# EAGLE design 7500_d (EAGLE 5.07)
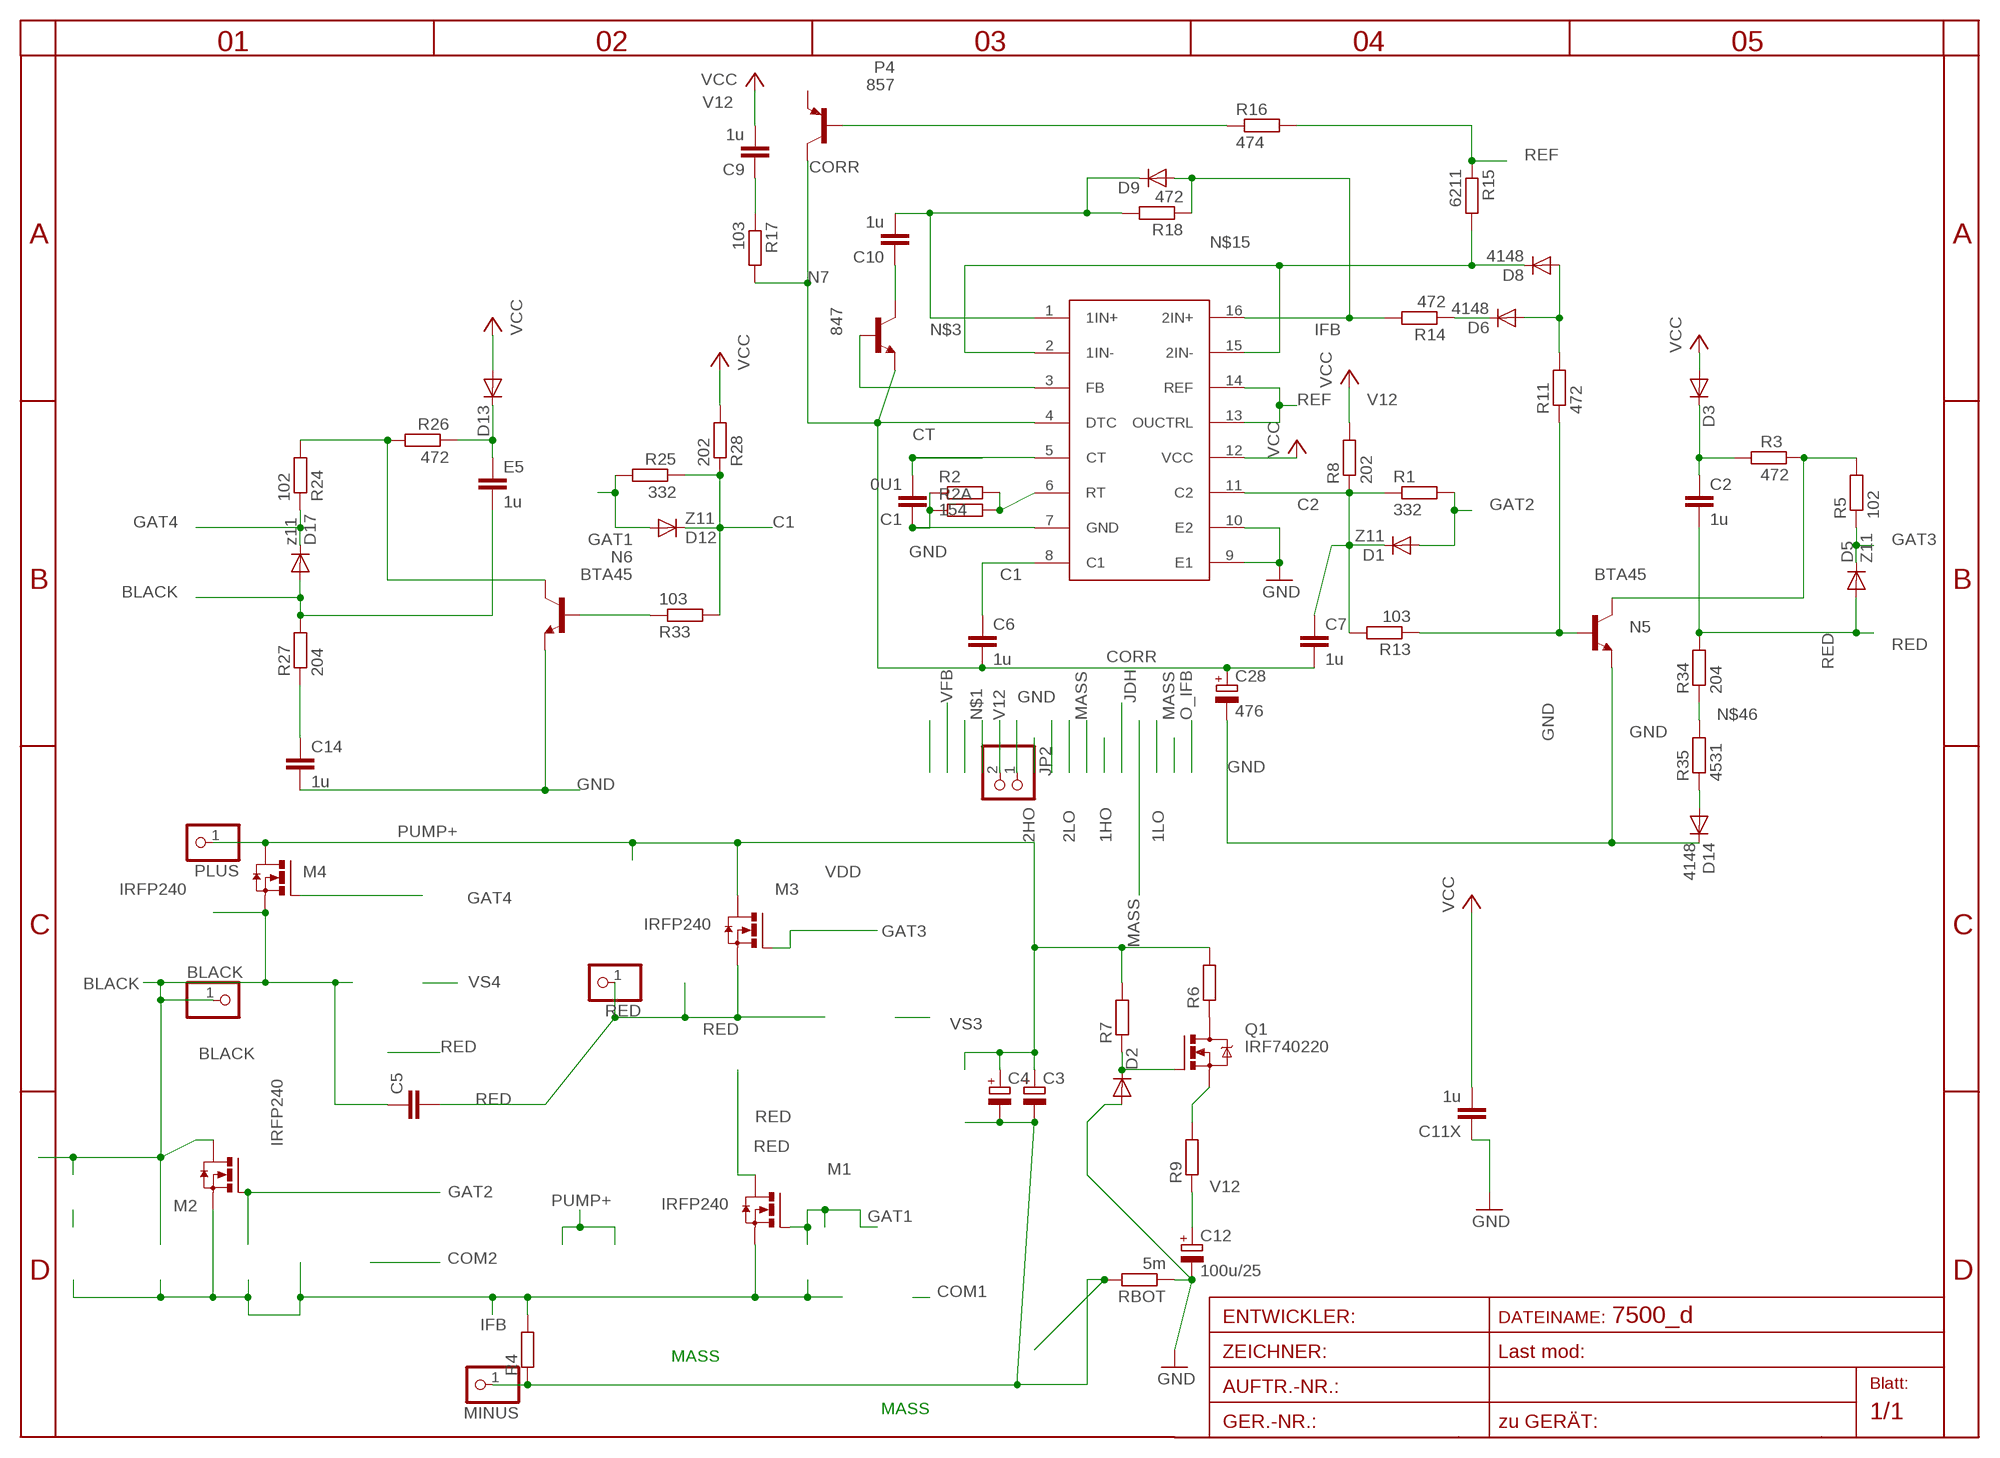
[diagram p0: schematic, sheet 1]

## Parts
7500  AZ7500SO16  [SO16]
BLACK  PINHD-1X12MM2  [1X2MM2]
C1  0U1  C-EUC0805  [C0805]
C2  1u  C-EUC1206  [C1206]
C3  CPOL-EUE5-13  [E5-13]
C4  CPOL-EUE5-13  [E5-13]
C5  C-EU050-024X044  [C050-024X044]
C6  1u  C-EUC0805  [C0805]
C7  1u  C-EUC0805  [C0805]
C9  1u  C-EUC0805  [C0805]
C10  1u  C-EUC1206  [C1206]
C11X  1u  C-EUC1206  [C1206]
C12  100u/25  CPOL-EUD  [PANASONIC_D]
C14  1u  C-EUC1206  [C1206]
C28  476  CPOL-EUA  [PANASONIC_A]
D1  Z11  DIODE-MINIMELF  [MINIMELF]
D2  DIODE-MINIMELF  [MINIMELF]
D3  DIODE-SMA-DO214  [SMA-DO214AC]
D5  Z11  DIODE-MINIMELF  [MINIMELF]
D6  4148  DIODE-MINIMELF  [MINIMELF]
D8  4148  DIODE-MINIMELF  [MINIMELF]
D9  DIODE-MINIMELF  [MINIMELF]
D12  Z11  DIODE-MINIMELF  [MINIMELF]
D13  DIODE-SMA-DO214  [SMA-DO214AC]
D14  4148  DIODE-MINIMELF  [MINIMELF]
D17  z11  DIODE-MINIMELF  [MINIMELF]
E5  1u  C-EUC1206  [C1206]
JP2  PINHD-1X2STR  [1X02]
M1  IRFP240  [TO247BV]
M2  IRFP240  [TO247BV]
M3  IRFP240  [TO247BV]
M4  IRFP240  [TO247BV]
MINUS  PINHD-1X12MM2  [1X2MM2]
N5  BTA45  SMBTA45HV  [SOT23HV]
N6  BTA45  SMBTA45HV  [SOT23HV]
N7  847  BC847ALT1SMD  [SOT23]
P4  857  BC857ALT1SMD  [SOT23-BEC]
PLUS  PINHD-1X12MM2  [1X2MM2]
Q1  IRF740220  [TO220BV]
R1  332  R-EU_R0805  [R0805]
R2  154  R-EU_R0805  [R0805]
R2A  R-EU_R0805  [R0805]
R3  472  R-EU_R0805  [R0805]
R4  R-EU_0309/10  [0309/10]
R5  102  R-EU_R1206  [R1206]
R6  R-EU_0207/10  [0207/10]
R7  R-EU_0207/10  [0207/10]
R8  202  R-EU_R0805  [R0805]
R9  R-EU_0207/12  [0207/12]
R11  472  R-EU_R0805  [R0805]
R13  103  R-EU_R0805  [R0805]
R14  472  R-EU_R0805  [R0805]
R15  6211  R-EU_R1206  [R1206]
R16  474  R-EU_R1206  [R1206]
R17  103  R-EU_R1206  [R1206]
R18  472  R-EU_R0805  [R0805]
R24  102  R-EU_R1206  [R1206]
R25  332  R-EU_R0805  [R0805]
R26  472  R-EU_R0805  [R0805]
R27  204  R-EU_R1206  [R1206]
R28  202  R-EU_R0805  [R0805]
R33  103  R-EU_R0805  [R0805]
R34  204  R-EU_R0805  [R0805]
R35  4531  R-EU_R0805  [R0805]
RBOT  5m  R-EU_0204/5  [0204/5]
RED  PINHD-1X12MM2  [1X2MM2]

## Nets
BLACK: BLACK.1 C5.1 D17.A E5.2 M2.D M4.S R27.2
C1: 7500.8(C1) C6.1 D12.C R25.1 R28.1 R33.2
C2: 7500.11(C2) C7.1 D1.C R1.1 R8.1 R13.2
CORR: 7500.4(DTC) C6.2 C7.2 C28.+ N7.2(E) P4.C R17.2
CT: 7500.5(CT) C1.2
GAT1: D12.A M1.G R25.2
GAT2: D1.A M2.G R1.2
GAT3: D5.C M3.G R5.1
GAT4: D17.C M4.G R24.1
GND: 7500.7(GND) 7500.9(E1) 7500.10(E2) C1.1 C11X.1 C12.- C14.2 C28.- D2.A D14.C JP2.1 N5.2(E) N6.2(E) R2.1 R2A.1 RBOT.1
IFB: 7500.16(2IN+) D9.A M1.S M2.S R4.2 R14.2 R18.1
MASS: C3.- C4.- MINUS.1 R4.1 RBOT.2
N$3: 7500.1(1IN+) C10.2 D9.C R18.2
N$4: C2.1 D3.K(C) R3.1
N$5: N5.3(C) R3.2 R5.2
N$7: Q1.D R6.1
N$8: D2.C Q1.G R7.1
N$11: N5.1(B) R11.1 R13.1
N$13: D6.A D8.A R11.2
N$15: 7500.2(1IN-) 7500.15(2IN-) D8.C R15.2
N$36: D6.C R14.1
N$37: P4.B R16.1
N$38: 7500.6(RT) R2.2 R2A.2
N$39: C9.1 R17.1
N$40: 7500.3(FB) N7.1(B)
N$41: C10.1 N7.3(C)
N$42: D13.K(C) E5.1 R26.1
N$43: N6.3(C) R24.2 R26.2
N$44: N6.1(B) R33.1
N$45: C14.1 R27.1
N$46: R34.1 R35.2
N$47: D14.A R35.1
PUMP+: C3.+ C4.+ M3.D M4.D PLUS.1 R6.2 R7.2
RED: C2.2 C5.2 D5.A M1.D M3.S R34.2 RED.1
REF: 7500.13(OUCTRL) 7500.14(REF) R15.1 R16.2
V12: 7500.12(VCC) C9.2 C11X.2 C12.+ D3.A D13.A JP2.2 R8.2 R9.1 R28.2 ; supply symbol labelled VCC
WAE: Q1.S R9.2
Unconnected: P4.E

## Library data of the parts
7500 = az7500:AZ7500
BLACK MINUS PLUS RED = pinhead:PINHD-1X1: PIN HEADER
C1 C2 C5-C7 C9 C10 C11X C14 E5 = rcl:C-EU: CAPACITOR, European symbol
C3 C4 C12 C28 = rcl:CPOL-EU: POLARIZED CAPACITOR, European symbol
D1-D3 D5 D6 D8 D9 D12-D14 D17 = diode:DIODE-: DIODE
JP2 = pinhead:PINHD-1X2: PIN HEADER
M1-M4 = transistor-power:IRFP240: HEXFET Power MosFet Source: http://www.irf.com/
N5 N6 = transistor-npn:SMBTA45
N7 = transistor-npn:BC847*: NPN Transistor
P4 = transistor-pnp:BC857*: PNP Transistror
Q1 = transistor-power:IRF740: N-CHANNEL MOS FET
R1 R2 R2A R3-R9 R11 R13-R18 R24-R28 R33-R35 RBOT = rcl:R-EU_: RESISTOR, European symbol

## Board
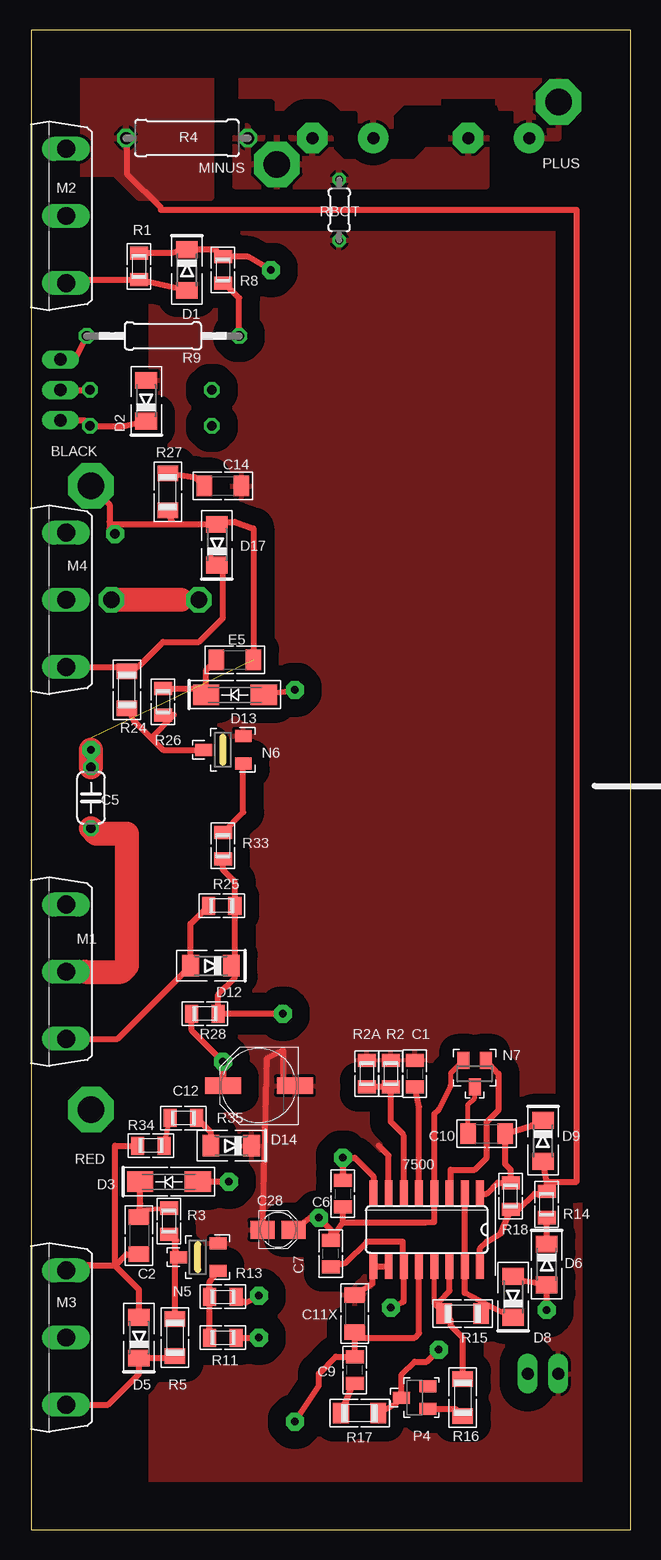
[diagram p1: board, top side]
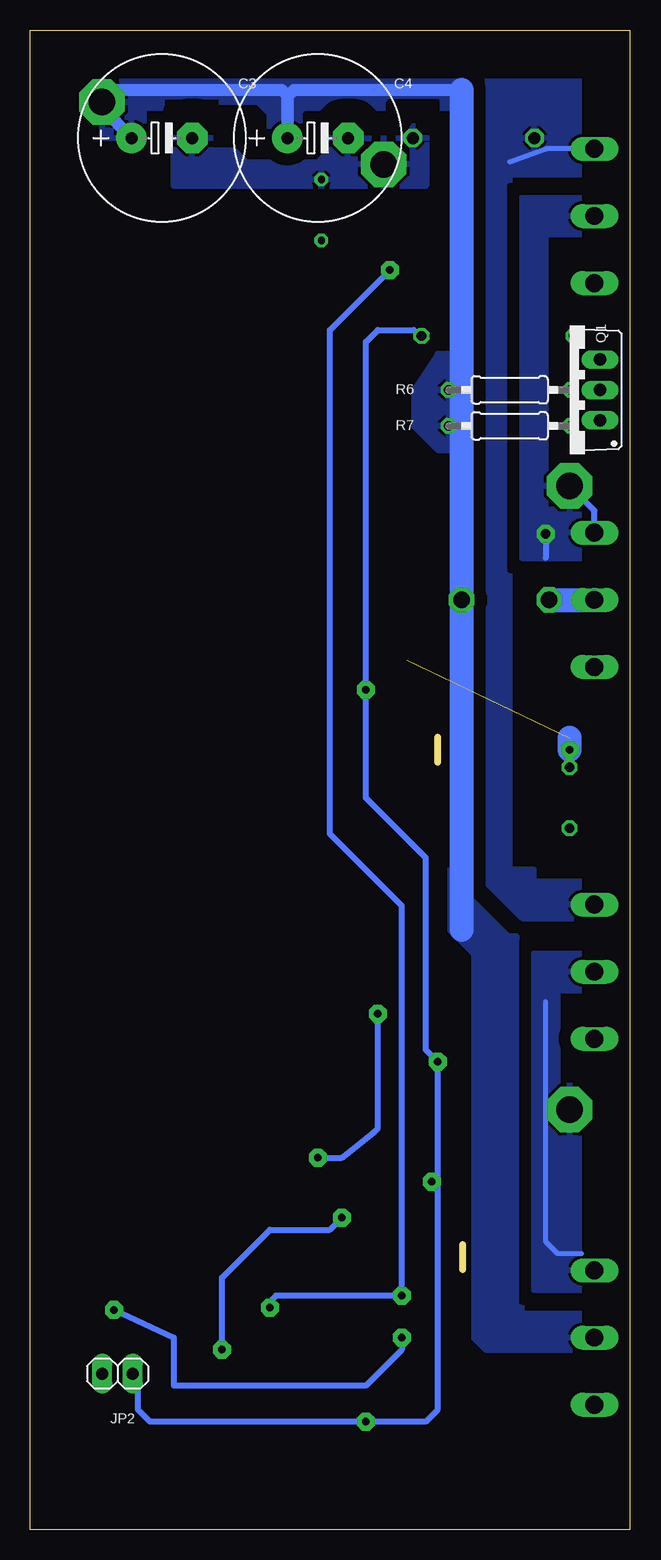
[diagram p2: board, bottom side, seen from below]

Size 50 x 125 mm. Coordinates in mm from the lower left corner, seen from the top.
Outline: 0,0 50,0 50,125 0,125 0,0
Copper layers (1*16): Top 0.035mm / dielectric 1.5mm / Bottom 0.035mm
Design rules "default *": minimum track width 10mil, minimum drill 20mil, track to track 8mil, track to pad 8mil, pad to pad 8mil, via to via 8mil, smd to smd 8mil, copper to edge 4mm, drill to drill 8mil, minimum pad ring 10mil, minimum via ring 8mil, stop-mask expansion 4mil, vias tented up to drill 0mil, thermal gap 10mil

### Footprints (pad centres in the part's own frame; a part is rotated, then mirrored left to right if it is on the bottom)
SO16 = smd 2.032 x 0.66: 1 -3.073,4.445; 2 -3.073,3.175; 3 -3.073,1.905; 4 -3.073,0.635; 5 -3.073,-0.635; 6 -3.073,-1.905; 7 -3.073,-3.175; 8 -3.073,-4.445; 9 3.073,-4.445; 10 3.073,-3.175; 11 3.073,-1.905; 12 3.073,-0.635; 13 3.073,0.635; 14 3.073,1.905; 15 3.073,3.175; 16 3.073,4.445
1X2MM2 = drill 2.2 pad 3.81 octagon: 1 0,0
C0805 = smd 1.1 x 1.5: 1 -1.1,0; 2 1.1,0
C1206 = smd 1.3 x 1.7: 1 -1.55,0; 2 1.55,0
E5-13 = drill 1 pad 2.54 round: + -2.54,0 | drill 1 pad 2.54 octagon: - 2.54,0
C050-024X044 = drill 0.8 octagon: 1 -2.54,0; 2 2.54,0
PANASONIC_D = smd 3 x 1.4: + 3,0; - -3,0
PANASONIC_A = smd 2 x 1.5: + 1.3,0; - -1.3,0
MINIMELF = smd 1.4 x 1.8: A 1.7,0; C -1.7,0
SMA-DO214AC = smd 2.2 x 1.7: A 2.4,0; K -2.4,0
1X02 = drill 1 pad 1.676 long: 1 -1.27,0; 2 1.27,0
TO247BV = drill 1.499 long: D 0,-2.921; G -5.588,-2.921; S 5.588,-2.921
SOT23HV = smd 1 x 1.4: 1 -1.15,-1.7; 2 1.15,-1.7; 3 0,1.6
SOT23 = smd 1 x 1.4: 1 -0.95,-1.1; 2 0.95,-1.1; 3 0,1.1
SOT23-BEC = smd 1 x 1.4: B -0.95,-1.1; C 0,1.1; E 0.95,-1.1
TO220BV = drill 1.016 long: D 0,-2.54; G -2.54,-2.54; S 2.54,-2.54
R0805 = smd 1.1 x 1.5: 1 -1.1,0; 2 1.1,0
0309/10 = drill 1 octagon: 1 -5.08,0; 2 5.08,0
R1206 = smd 1.3 x 1.7: 1 -1.55,0; 2 1.55,0
0207/10 = drill 0.8 octagon: 1 -5.08,0; 2 5.08,0
0207/12 = drill 0.813 octagon: 1 -6.35,0; 2 6.35,0
0204/5 = drill 0.6 octagon: 1 -2.54,0; 2 2.54,0

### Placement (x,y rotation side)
7500  33,25 270 top
BLACK  5,87 0 top
C1  32,38 270 top
C2  9,24.5 270 top
C3  39,116 0 bottom
C4  26,116 0 bottom
C5  5,61 270 top
C6  26,28 270 top
C7  25,23 90 top
C9  27,13.3 90 top
C10  38,33 0 top
C11X  27,18 270 top
C12  19,37 180 top
C14  16,87 0 top
C28  20.6,25 0 top
D1  13,105 270 top
D2  9.6,94.1 90 top
D3  11.5,29 0 top
D5  9,16 90 top
D6  43,22.1 270 top
D8  40.2,19.4 90 top
D9  42.7,32.4 270 top
D12  15,47 180 top
D13  17,69.6 0 top
D14  16.7,32 180 top
D17  15.5,82.1 90 top
E5  17,72.5 0 top
JP2  42.7,13 0 bottom
M1  0,46.5 90 top
M2  0,109.5 90 top
M3  0,16 90 top
M4  0,77.5 90 top
MINUS  20.5,113.8 0 top
N5  13.9,22.7 90 top
N6  16,65 90 top
N7  37,38 180 top
P4  32,11 90 top
PLUS  44,119 0 top
Q1  5,95 90 bottom
R1  9,105.3 270 top
R2  30,38 270 top
R2A  28,38 270 top
R3  11.5,25.7 270 top
R4  13,116 180 top
R5  12,16 90 top
R6  10,95 180 bottom
R7  10,92 180 bottom
R8  16,105 270 top
R9  11,99.5 180 top
R11  16,16 0 top
R13  16,19.4 0 top
R14  43,27.1 90 top
R15  36,18 0 top
R16  36,11 90 top
R17  27.4,9.7 0 top
R18  40,27.8 90 top
R24  8,70 270 top
R25  15.9,52 180 top
R26  11,69 270 top
R27  11.4,86.5 270 top
R28  14.5,43 180 top
R33  16,57 270 top
R34  10,32 180 top
R35  12.7,34.3 180 top
RBOT  25.7,110 90 top
RED  5,35 0 top

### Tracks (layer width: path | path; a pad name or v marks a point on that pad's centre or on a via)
BLACK  (via drill 0.6 pad 1.5, 0.8 pad 1.5)  (1 unrouted)
  Top 0.5: E5.2 18.55,83.45 17,84 16.1,84 D17.A 11.85,83.8 | 11.85,83.8 R27.2 | BLACK.1 6.55,85.45 6.55,84 | 6.55,84 6.55,83.45 v7,83 | 11.85,83.8 6.75,83.8 6.55,84
  Top 2: C5.1 v5,65
  Bottom 0.5: M4.S 2.92,84.92 BLACK.1 | v7,83 7,81
  Bottom 2: v5,65 5,66
  pour Bottom (isolate 1): 2,111 9,111 9,81 1,81 1,85 7,85 7,108 1,108 1,109
C1  (via drill 0.6 pad 1.5)
  Top 0.5: 7500.8 28.55,29.45 27,31 26.1,31 C6.1 v26,31 | v21,43 R28.1 15.6,44.6 17,46 17,46.7 D12.C 17,47.3 R25.1 17,54 16,55 R33.2
  Bottom 0.5: v26,31 24,31 21.33,33.12 21,33.45 v21,43
C2  (via drill 0.6 pad 1.5)
  Top 0.5: R13.2 17.9,18.9 v19,19.5 | v30,18.5 31,19 31.09,19 7500.11 31,22.02 31,24 28,24 26.2,22.2 C7.1 | v20,105 18.1,106.1 R8.1 15.4,106.7 D1.C 11.7,106.4 R1.1
  Bottom 0.5: v20,105 25,100 25,58 19,52 v19,19.5 29.5,19.5 30,19 v30,18.5
CORR  (via drill 0.6 pad 1.5)
  Top 0.406: 35,37 35,38.05 N7.2
  Top 0.5: 35,37 34,35 33.63,34.63 7500.4 33.63,25.64 32.9,25.6 26,25.6 | 26,25.6 C7.2 25,25 v24,26 23.3,26 C28.+ | 26,25.6 C6.2 | v34,15 33,14 32,14 30.9,12.9 P4.C 30.35,10.45 R17.2
  Bottom 0.5: v34,15 34,21 30,25 25,25 v24,26
CT
  Top 0.5: 7500.5 32.37,35.27 C1.2
GAT1
  Top 0.5: M1.G 7.21,40.91 D12.A 13.3,50.5 R25.2
GAT2
  Top 0.5: D1.A 9.1,104.2 R1.2 3.21,104.2 M2.G
GAT3
  Top 0.5: M3.G 6.41,10.41 9,13 D5.C 11.85,14.3 R5.1
GAT4
  Top 0.5: D17.C 15,81 16,80 16,76 14,74 11,74 8.91,71.91 8.36,71.91 R24.1 7.64,71.91 M4.G
GND
  Top 0.5: 7500.7 29.82,31.18 29,32 | 7500.10 7500.9 28.45,20.5 C11X.1 | C28.- 19.7,39.3 21,40 21,37 C12.-
  pour Top (isolate 1.5): 10,2 10,110 48,110 48,2
IFB
  Top 0.5: 43,29 D9.A | 7500.16 37.45,23.45 38,24 39.2,24.7 R18.1 40.7,26.7 42,28 42.8,28 R14.2 43,29 | 43,29 45.5,29 45.5,110 10.83,110 10.83,110.17 8,113 8,115.92 R4.2
  Bottom 0.406: M2.S 6.91,115.09 10,114
  pour Bottom (isolate 1, rank 2): 2,122 12,122 12,54 9,51 1,51 1,54 8,54 8,55 10,55 10,113 2,113
  pour Top (isolate 1, rank 2): 4,121 15,121 15,111 9,111 7,113 4,113
MASS
  Bottom 0.406: C3.- 36.46,116.46 | C4.- 24,115.46
  Bottom 1: 20.24,113.54 MINUS.1
  pour Bottom (isolate 1, rank 2): 17,117 17,112 38,112 38,117 35,117 35,115 33,115 32,114 26,114 25,115 25,116 19,116 18,117
  pour Top (isolate 1, rank 2): 17,117 17,112 38,112 38,117 35,117 35,115 33,115 32,114 26,114 25,115 25,116 19,116 18,117
N$3
  Top 0.5: D9.C 41.8,33.7 C10.2 39.55,30.45 40,30 R18.2 38.9,28.9 38,28 37.52,28 7500.1
N$4
  Top 0.406: 9,26.65 R3.1
  Top 0.5: 9,26.65 C2.1 9.1,27.15 D3.K
N$5
  Top 0.5: R5.2 12,22.6 N5.3 12,23.4 12,24 12.1,24.1 R3.2
N$7
  Top 0.5: Q1.D R6.1
N$8
  Top 0.5: Q1.G 4.46,92.46 R7.1 7.7,92 D2.C
N$11
  Top 0.5: R11.1 R13.1 14.9,20.65 N5.1
N$13  (via drill 0.6 pad 1.5)
  Top 0.5: R11.2 v19,16 | v43,18.3 D6.A 40.4,20.8 D8.A
  Bottom 0.5: v19,16 19,15 22,12 38,12 38,16 v43,18.3
N$15
  Top 0.5: 7500.2 7500.15 36.17,19.73 38.08,18.73 | 38.08,18.73 D8.C | R15.2 37.55,18.3 38.08,18.73
N$36
  Top 0.5: D6.C R14.1
N$37
  Top 0.5: P4.B 35.4,10.05 R16.1
N$38
  Top 0.5: 7500.6 31.09,32.8 31,33 30,34 R2.2 R2A.2
N$39
  Top 0.5: C9.1 26.75,11.9 R17.1
N$40
  Top 0.5: N7.1 38.95,38 39,38 39,35 38,34 38,31 37,30 35,30 35,28.17 7500.3
N$41
  Top 0.406: C10.1 36.45,35.45 37,36 N7.3
N$42
  Top 0.5: R26.1 14.4,70.1 D13.K 14.6,71.65 E5.1
N$43
  Top 0.5: R24.2 8.55,67.45 10,66 | 10,66 11,65 N6.3 | R26.2 11.9,67.9 10,66
N$44
  Top 0.5: N6.1 17.7,59.8 R33.1
N$45
  Top 0.5: R27.1 13.6,87.75 C14.1
N$46
  Top 0.406: R34.1 R35.2
N$47
  Top 0.5: D14.A 15,33.1 R35.1
PUMP+  (via drill 1.4 pad 1.5)
  Top 0.5: v14,77.5 12.5,77.5
  Top 2: 12.5,77.5 v6.7,77.5
  Bottom 0.5: 14,92 R7.2
  Bottom 1: 14,120 28,120 28.54,119.46 C4.+ 28.54,119.54 29,120 43,120 PLUS.1 44,118.46 C3.+
  Bottom 2: 14,50 v14,77.5 14,92 14,120 | v6.7,77.5 M4.D
  pour Bottom (isolate 1, rank 3): 1,18 9,18 9,49 15,55 15,50 13,48 13,16 12,15 1,15
  pour Bottom (isolate 2, rank 3): 44,116 44,121 12,121 12,116 13,115 14,115 15,116 15,118 27,118 27,115 30,115 30,118 31,119 39,119 40,116
  pour Bottom (isolate 1, rank 2): 15,98 16,98 18,95 18,92 16,90 14,90 14,97
  pour Top (isolate 2, rank 3): 44,116 44,121 12,121 12,116 13,115 14,115 15,116 15,118 27,118 27,115 30,115 30,118 31,119 39,119 40,116
RED
  Top 0.406: 7,22 3.16,22.16
  Top 0.5: D5.A 9,20 7,22 | 7,22 4,22 | 4,22 3.57,22 | 4,22 3,22.32 3.16,22.16 3.16,21.83 M3.S | C2.2 7.95,22.95 7,22 | R34.2 7,32 7,22
  Top 1: M1.D 4.5,46.5
  Top 2: 4.5,46.5 7.5,46.5 8,47 8,58 5.46,58 C5.2
  Bottom 0.406: 7,44 7,24 6,23 4,23
  pour Bottom (isolate 1): 2,48 8,48 8,20 2,20 2,23 4,23 4,37 6,37 6,45 2,45
REF
  Top 0.406: 7500.13 33.63,18.82 R15.1
  Top 0.5: 7500.14 34.91,19.91 34,19 34,18.45 R15.1 35,17.45 35,17 36,16 R16.2
V12  (via drill 0.6 pad 1.5)
  Top 0.5: 7500.12 32.37,16.36 32,16 27,16 | 27.45,16 C11X.2 27,16 | D13.A 21.9,69.9 v22,70 | R9.1 17.35,102.65 16,104 R8.2 | 27,16 C9.2 25.4,14.4 24,13 24,12 v22,9 | C12.+ v16,39 13.4,41.6 R28.2 | v16.5,29 D3.A
  Bottom 0.5: 16,29 16,10 17,9 v22,9 40,9 41,10 41,12.57 JP2.2 | 16,29 v16,39 17,40 17,56 22,61 v22,70 22,99 21,100 18,100 17.5,99.5 R9.1 | 16,29 v16.5,29
WAE
  Top 0.5: Q1.S 3.69,97.54 R9.2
